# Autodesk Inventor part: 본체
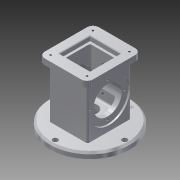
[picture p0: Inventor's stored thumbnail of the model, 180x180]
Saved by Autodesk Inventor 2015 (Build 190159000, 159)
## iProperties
Created: 2019-08
Part Number: 본체
Material: 알루미늄 6061
Document SubType Name: Modeling
Designer: now
Density: 2.7 g/cm^3
Appearance: 알루미늄 - 평지
Mass: 1041.24 g
Surface Area: 795.125 cm^2
Volume: 385.644 cm^3
Author: now
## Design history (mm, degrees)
sketch "스케치1"
  geometry: C1 r 67.5 at (0, 0); 1 further point
  constraints: 1 centre point, 1 coincident
  dimensions: "d0" = 135 diameter of C1
extrude "돌출1" new body sketch "스케치1" distance "d1" = 10; taper "d2" = 0 deg
sketch "스케치2"
  geometry: L1 (-33, 37)-(33, 37); L2 (33, 37)-(33, -37); L3 (33, -37)-(-33, -37); L4 (-33, -37)-(-33, 37); L5 (-33, 37)-(33, -37); L6 (33, 37)-(-33, -37); C1 r 67.5 at (0, 0) reference
  constraints: 12 end point, 2 midpoint, 2 parallel, 1 horizontal, 1 perpendicular
  dimensions: "d3" = 66 distance of L1.start L1.end; "d4" = 74 distance of L3.end L1.start
extrude "돌출2" join sketch "스케치2" distance "d5" = 88; taper "d6" = 0 deg
sketch "스케치3"
  geometry: L1 (-41, 46)-(41, 46); L2 (41, 46)-(41, -46); L3 (41, -46)-(-41, -46); L4 (-41, -46)-(-41, 46); L5 (-41, 46)-(41, -46); L6 (41, 46)-(-41, -46); 1 further point
  constraints: 12 end point, 2 midpoint, 2 parallel, 1 horizontal, 1 perpendicular
  dimensions: "d7" = 92 distance of L3.end L1.start; "d8" = 82 distance of L1.start L1.end
extrude "돌출3" join sketch "스케치3" distance "d9" = 10; taper "d10" = 0 deg
fillet "모깎기1" dims "d11" = 10
fillet "모깎기2" dims "d12" = 3
sketch "스케치4"
  geometry: L1 (10, -33.5)-(10, 101.5) reference; C1 r 35 at (-44, 34); 1 further point
  constraints: 1 centre point, 1 horizontal alignment
  dimensions: "d13" = 70 diameter of C1; "d14" = 54 distance from line of L1 C1.centre
extrude "돌출4" cut sketch "스케치4" distance "d15" = 3; taper "d16" = 0 deg
sketch "스케치5"
  geometry: C1 r 35 at (0, 0) reference; 1 further point
hole "구멍1" sketch "스케치5" at (0, 0) diameter "d17" = 48; stored, may be unused: countersink angle "d21" = 90 deg, drill point angle "d23" = 118 deg; dims "d18" = 6, "d19" = 4, "d20" = 2, "d22" = 8
sketch "스케치7"
  geometry: L1 (-26, 26)-(26, 26); L2 (26, 26)-(26, -26); L3 (26, -26)-(-26, -26); L4 (-26, -26)-(-26, 26); L5 (-26, 26)-(26, -26); L6 (26, 26)-(-26, -26); 1 further point
  constraints: 12 end point, 2 midpoint, 2 parallel, 1 horizontal, 1 perpendicular
  dimensions: "d35" = 52 distance of L1.start L1.end; "d36" = 52 distance of L1.end L2.end
extrude "돌출5" cut sketch "스케치7" distance "d37" = 8; taper "d38" = 0 deg
sketch "스케치8"
  geometry: L1 (-22, -22)-(22, -22); L2 (22, -22)-(22, 22); L3 (22, 22)-(-22, 22); L4 (-22, 22)-(-22, -22); L5 (-22, -22)-(22, 22); L6 (22, -22)-(-22, 22); 1 further point
  constraints: 12 end point, 2 midpoint, 2 parallel, 1 horizontal, 1 perpendicular
  dimensions: "d39" = 44 distance of L3.end L1.start; "d40" = 44 distance of L2.end L3.end
extrude "돌출6" cut sketch "스케치8" distance "d41" = 74; taper "d42" = 0 deg
chamfer "모따기1" distance "d43" = 1; stored, may be unused: second distance "d44" = 2, angle "d45" = 45 deg
chamfer "모따기2" distance "d46" = 1; stored, may be unused: second distance "d47" = 2, angle "d48" = 45 deg
sketch "스케치9"
  geometry: A1 r 10 centre (31, 36) between (41, 36) and (31, 46) reference; A2 r 10 centre (-31, 36) between (-31, 46) and (-41, 36) reference; A3 r 10 centre (-31, -36) between (-41, -36) and (-31, -46) reference; A4 r 10 centre (31, -36) between (31, -46) and (41, -36) reference; 1 further point
hole "구멍3" sketch "스케치9" at (-31, -36), (31, -36), (31, 36), (-31, 36) diameter "d49" = 3.242; stored, may be unused: countersink angle "d53" = 90 deg, drill point angle "d55" = 118 deg; dims "d50" = 4, "d51" = 4, "d52" = 2, "d54" = 6
sketch "스케치10"
  geometry: C1 r 67.5 at (0, 0) reference; 3 further points
  constraints: 2 horizontal alignment, 1 vertical alignment
  dimensions: "d56" = 59 distance of C1.centre point (-59, 0); "d57" = 59 distance of point (59, 0) C1.centre; "d58" = 59 distance of C1.centre point (0, -59)
hole "구멍4" sketch "스케치10" at (-59, 0), (59, 0), (0, -59) diameter "d60" = 9; stored, may be unused: countersink angle "d64" = 90 deg, drill point angle "d66" = 0 deg; dims "d61" = 4, "d62" = 4, "d63" = 2, "d65" = 6
fillet "모깎기4" dims "d68" = 3
sketch "스케치11"
  geometry: C1 r 67.5 at (0, 0) reference; C2 r 25 at (0, 0)
  constraints: 1 centre point, 1 coincident
  dimensions: "d69" = 50 diameter of C2
extrude "돌출7" cut sketch "스케치11" distance "d70" = 18; taper "d71" = 0 deg
sketch "스케치12"
  geometry: C1 r 25 at (0, 0) reference; C2 r 12.5 at (0, 0)
  constraints: 1 centre point, 1 coincident
  dimensions: "d72" = 25 diameter of C2
extrude "돌출8" cut sketch "스케치12" stored distance "d73" = 18; taper "d74" = 0 deg
fillet "모깎기5" dims "d75" = 3
fillet "모깎기6" dims "d76" = 3
sketch "스케치13"
  geometry: C1 r 24 at (0, 0) reference; 2 further points
  constraints: 1 horizontal alignment
  dimensions: "d77" = 29 distance of C1.centre point (-29, 0)
hole "구멍5" sketch "스케치13" at (-29, 0) diameter "d78" = 3.242; stored, may be unused: countersink angle "d82" = 90 deg, drill point angle "d84" = 118 deg; dims "d79" = 4, "d80" = 4, "d81" = 2, "d83" = 6
sketch "스케치15"
  geometry: L1 (97.5, 10)-(-37.5, 10) reference; 3 further points
  constraints: 2 vertical alignment
  dimensions: "d92" = 43 distance of point (30, -27) point (30, -70); "d93" = 37 distance from line of L1 point (30, -27)
hole "구멍6" sketch "스케치15" at (30, -70), (30, -27) diameter "d94" = 4.917; stored, may be unused: countersink angle "d98" = 90 deg, drill point angle "d100" = 0 deg; dims "d95" = 12, "d96" = 4, "d97" = 2, "d99" = 20
fillet "모깎기7" dims "d101" = 3
chamfer "모따기3" distance "d102" = 3; stored, may be unused: second distance "d103" = 2, angle "d104" = 45 deg
sketch "스케치16"
  geometry: C1 r 4.5 at (-59, 0) reference; C2 r 64.5 at (0, 0) reference; C3 r 4.5 at (0, 59); A1 r 59 centre (0, 0) between (-59, 0) and (0, 59)
  constraints: 2 centre point, 2 point on circle, 1 coincident, 1 vertical alignment, 1 other
  dimensions: "d105" = 9 diameter of C3
feature "엠보싱2" sketch "스케치16" dims "d1" = 10, "d9" = 10, "d106" = 0.5, "d107" = 0
node "솔리드1"
mirror "대칭1"
pattern_circular "원형 패턴2" dims angle "d86" = 360 deg
mirror "대칭3"
